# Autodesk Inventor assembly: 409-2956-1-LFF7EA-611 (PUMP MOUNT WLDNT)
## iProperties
Created: 2010-06
Part Number: 409-2956-1-LFF7EA-611 (PUMP MOUNT WLDNT)
Document SubType Name: Weldment
Designer: S. Boerckel
Weld Material: Welded Aluminum-6061
Mass: 194904 g
Surface Area: 33460.6 cm^2
Volume: 24797 cm^3
Density: 7.86 g/cm^3
Description: PUMP MOUNT
Material: WELDMENT
SMR: =<Material>
Author: S. Boerckel
Revision Number: 0
Subject: LIQUID FUEL FORWARDING PUMP SKID-7EA
